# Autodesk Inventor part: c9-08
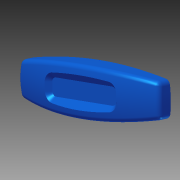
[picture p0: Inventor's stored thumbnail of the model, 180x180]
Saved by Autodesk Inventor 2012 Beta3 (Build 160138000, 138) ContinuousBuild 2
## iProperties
Created: 2010-12
Part Number: c9-08
Material: Default
Document SubType Name: Modeling
Designer: Beta-8540w
Density: 1 g/cm^3
Author: Beta-8540w
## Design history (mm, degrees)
sketch "Sketch1"
  geometry: L1 (-60, -12)-(60, -12); L2 (60, -12)-(60, 12); L3 (60, 12)-(-60, 12); L4 (-60, 12)-(-60, -12); A1 r 350 centre (0, -332.819) between (60, 12) and (-60, 12); A2 r 350 centre (0, 332.819) between (-60, -12) and (60, -12); 3 further points
  constraints: 8 end point, 4 point on circle, 2 centre point, 2 midpoint, 2 parallel, 1 equal radius, 1 horizontal, 1 horizontal alignment, 1 perpendicular, 1 vertical alignment
  dimensions: "d0" = 120 distance of L3.end L2.end; "d1" = 24 distance of L2.end L1.end; "d2" = 350 radius of A1
workplane "Work Plane4"
sketch "Sketch5"
  geometry: L1 (-60, 12)-(-60, -12) reference; L2 (60, -12)-(60, 12) reference; L3 (-58, 10.314)-(-58, -10.314); L4 (58, -10.314)-(58, 10.314); A1 r 350 centre (0, 332.819) between (-60, -12) and (60, -12) reference; A2 r 350 centre (0, -332.819) between (60, 12) and (-60, 12) reference; A3 r 348 centre (0, 332.819) between (-58, -10.314) and (58, -10.314); A4 r 348 centre (0, -332.819) between (58, 10.314) and (-58, 10.314); 1 further point
  constraints: 4 end point, 4 point on circle, 2 centre point, 3 other
  dimensions: "d37" = 2 distance between parallel lines of L2 L4
sketch "Sketch6"
  geometry: L1 (-60, 0)-(60, 0); L2 (60, 0)-(58.843, 22.085); L3 (-60, 0)-(-58.779, 23.307); A1 r 691.758 centre (630.81, -36.204) between (-60, 0) and (-58, -100); A2 r 691.758 centre (-630.81, -36.204) between (58, -100) and (60, 0); 1 further point
  constraints: 6 end point, 4 point on circle, 2 centre point, 2 tangent, 1 horizontal
  dimensions: "d53" = 87 deg angle of L1 L3; "d54" = 87 deg angle of L1 L2 (= d53)
sketch "Sketch7"
  geometry: L1 (17.181, 0)-(12, 0) reference; L2 (15.181, -100)-(10.314, -100) reference; L3 (17.181, 0)-(16.768, 11.838); A1 r 911.322 centre (-893.585, -31.805) between (15.181, -100) and (17.181, 0); 1 further point
  constraints: 2 end point, 2 point on circle, 1 centre point, 1 tangent
  dimensions: "d56" = 88 deg angle of L1 L3
feature "LoftSrf2" sketch "Sketch5", "Sketch6", "Sketch7" dims "d57" = 0, "d58" = 90 deg, "d59" = 0, "d60" = 90 deg, "d61" = 0, "d62" = 90 deg, "d63" = 0, "d64" = 90 deg, "d65" = 0, "d66" = 90 deg
sketch "Sketch2"
  geometry: L1 (-75, -16)-(75, -16); L2 (-75, -60)-(75, -60); A1 r 183.781 centre (0, -183.781) between (75, -16) and (-75, -16); 2 further points
  constraints: 4 end point, 3 point on circle, 1 centre point, 1 coincident, 1 horizontal, 1 parallel
  dimensions: "d5" = 16 distance from line of point (0, 0) L1; "d7" = 60 distance from line of point (0, 0) L2; "d55" = 150 distance of L1.start L1.end
feature "RevolutionSrf1" sketch "Sketch2" dims angle "d8" = 40 deg
patch "Boundary Patch1" dims "d13" = 0, "d67" = 0, "d68" = 0, "d69" = 0, "d70" = 0
workplane "Work Plane1"
sketch "Sketch3"
  geometry: L1 (52, -85)-(52, -73); L2 (38, -73)-(38, -85); A1 r 7 centre (45, -73) between (52, -73) and (38, -73); A2 r 7 centre (45, -85) between (38, -85) and (52, -85); 1 further point
  constraints: 4 end point, 4 point on circle, 4 tangent, 2 centre point, 1 parallel, 1 vertical
  dimensions: "d15" = 12 distance of L1.start L1.end; "d16" = 7 radius of A1; "d50" = 45 horizontal distance of A1.centre point (0, 0); "d51" = 85 vertical distance of point (0, 0) A2.centre
extrude_surface "ExtrusionSrf2" sketch "Sketch3" dims "d19" = 14, "d20" = 5 deg
pattern_linear "Rectangular Pattern1" dims "d23" = 90
workplane "Work Plane2"
feature "Sculpt1"
sketch "Sketch4"
  geometry: L1 (-24.5, 6)-(24.5, 6); L2 (27.5, 3)-(27.5, -3); L3 (24.5, -6)-(-24.5, -6); L4 (-27.5, -3)-(-27.5, 3); A1 r 3 centre (-24.5, 3) between (-24.5, 6) and (-27.5, 3); A2 r 3 centre (24.5, 3) between (27.5, 3) and (24.5, 6); A3 r 3 centre (24.5, -3) between (24.5, -6) and (27.5, -3); A4 r 3 centre (-24.5, -3) between (-27.5, -3) and (-24.5, -6); 6 further points
  constraints: 8 end point, 8 point on circle, 8 tangent, 6 point on line, 4 centre point, 3 equal radius, 2 midpoint, 2 parallel, 1 horizontal, 1 horizontal alignment, 1 perpendicular, 1 vertical alignment
  dimensions: "d28" = 55 distance of point (27.5, -6) point (-27.5, -6); "d29" = 12 distance of point (27.5, 6) point (27.5, -6); "d30" = 3 radius of A1
extrude_surface "ExtrusionSrf6" sketch "Sketch4" dims "d31" = 14, "d32" = 45 deg
patch "Boundary Patch2" dims "d33" = 0, "d34" = 0
fillet "Fillet1" dims "d79" = 4, "d80" = 3, "d81" = 1
feature "Sculpt2"
node "Splitting Plane 1"
shell "Shell1" dims "d83" = 2
split "Split1"
  body "Solid1"
feature "Lip1" dims "d188" = 1, "d189" = 1, "d190" = 0, "d191" = 0, "d192" = 0, "d193" = 0
feature "Lip2" dims "d194" = 1, "d195" = 1, "d196" = 0, "d197" = 0, "d198" = 0, "d199" = 0.5
split "Split3"
  node "Back"
sketch "Sketch9"
  geometry: L1 (50.167, -73)-(50.167, -85) reference; L2 (39.833, -85)-(39.833, -73) reference; L3 (45, -73)-(45, -85); L4 (45, -85)-(39.833, -85); A1 r 5.167 centre (45, -73) between (50.167, -73) and (39.833, -73) reference; A2 r 5.167 centre (45, -85) between (39.833, -85) and (50.167, -85) reference; 5 further points
  constraints: 4 end point, 1 horizontal, 1 midpoint, 1 parallel, 1 perpendicular, 1 vertical, 3 other
  dimensions: "d86" = 90 distance of point (45, -79) point (-45, -79); "d89" = 40 distance of point (45, -79) point (45, -39)
  node "Projected Loop1"
feature "Boss1" dims "d92" = 0, "d93" = 0, "d94" = 7, "d95" = 2, "d96" = 0.5, "d97" = 6, "d98" = 1.25, "d99" = 3.5, "d100" = 2.5 deg, "d101" = 2.5 deg, "d102" = 2.5 deg, "d103" = 2.5 deg, "d104" = 90 deg, "d107" = 2, "d108" = 2, "d109" = 10, "d110" = 0, "d111" = 10 deg, "d112" = 2.5 deg, "d113" = 0, "d114" = 0, "d115" = 0, "d116" = 360 deg
feature "Boss2" dims "d117" = 3, "d118" = 0, "d119" = 6, "d120" = 3, "d121" = 9.5, "d122" = 2 deg, "d123" = 1 deg, "d126" = 2, "d127" = 2, "d128" = 10, "d129" = 0, "d130" = 10 deg, "d131" = 2.5 deg, "d132" = 0, "d133" = 0, "d134" = 0, "d135" = 360 deg
workplane "Work Plane6"
sketch "Sketch10"
  geometry: L1 (24, -85)-(-24, -85); L2 (-30, -79)-(-30, -51); L3 (-24, -45)-(24, -45); L4 (30, -51)-(30, -79); L5 (54.344, -100)-(-54.344, -100) reference; A1 r 6 centre (-24, -51) between (-24, -45) and (-30, -51); A2 r 6 centre (24, -51) between (30, -51) and (24, -45); A3 r 6 centre (24, -79) between (24, -85) and (30, -79); A4 r 6 centre (-24, -79) between (-30, -79) and (-24, -85); 5 further points
  constraints: 8 end point, 8 point on circle, 8 tangent, 6 point on line, 4 centre point, 3 equal radius, 2 parallel, 1 horizontal, 1 midpoint, 1 perpendicular, 1 vertical alignment
  dimensions: "d137" = 60 distance of point (-30, -45) point (30, -45); "d138" = 40 distance of point (-30, -85) point (-30, -45); "d139" = 15 distance between parallel lines of L5 L1; "d141" = 6 radius of A2
feature "Rest1" sketch "Sketch10" dims "d142" = 5, "d143" = 0, "d144" = 0, "d145" = 0, "d146" = 2 deg, "d147" = 2 deg, "d148" = 2
feature "Rule Fillet1" dims "d149" = 2, "d150" = 1
workplane "Work Plane7"
sketch "Sketch11" dims "d154" = 16, "d155" = 8, "d161" = 10, "d168" = 10
  geometry: L1 (-13, -39.858)-(-13, -90.142); L2 (-25.187, -85)-(29.449, -85); L3 (0, -39.858)-(0, -90.142); L4 (13, -39.858)-(13, -90.142); L5 (-25.187, -77)-(29.449, -77); L6 (-25.187, -69)-(29.449, -69); L7 (-25.187, -61)-(29.449, -61); L8 (-25.187, -53)-(29.449, -53); L9 (-25.187, -45)-(29.449, -45); C1 r 22.5 at (0, -65); 3 further points; 1 other entity
  constraints: 18 end point, 2 coincident, 2 vertical, 1 centre point, 1 horizontal, 1 midpoint, 1 perpendicular, 1 vertical alignment, 23 other
  dimensions: "d152" = 45 diameter of C1; "d153" = 65 distance of point (0, 0) C1.centre; "d158" = 13 distance of L1.start L3.start; "d165" = 8 distance of L2.start L5.start; "d170" = 4 distance from line of L7 point (0, -65)
feature "Grill1" sketch "Sketch11" dims "d173" = 2, "d174" = 0, "d175" = 1, "d176" = 2, "d177" = 0, "d178" = 1, "d179" = 0.5, "d180" = 0, "d181" = 2, "d182" = 1, "d183" = 2 deg, "d184" = 0, "d185" = 88.84492
sketch "Sketch12"
  geometry: L1 (-12.481, -61.203)-(12.401, -61.203); L2 (12.401, -61.203)-(12.401, -68.714); L3 (12.401, -68.714)-(-12.481, -68.714); L4 (-12.481, -68.714)-(-12.481, -61.203); 1 further point
  constraints: 2 other
emboss "Emboss1" sketch "Sketch12" dims "d0" = 120, "d1" = 24, "d2" = 350, "d186" = 0.5, "d187" = 0
sketch "Sketch13"
  geometry: L1 (0, 15.66)-(0, -14.781); 6 further points
  constraints: 2 end point, 1 coincident, 1 point on line, 1 vertical, 4 other
body "Srf2"
body "Srf3"
body "Srf4"
body "Srf5"
body "Srf6"
body "Srf7"
body "Srf8"
body "Srf9"
body "Srf11"
feature "Stitch Surface1"
body "Srf12"
extrude_surface "ExtrusionSrf3"
extrude_surface "ExtrusionSrf4"
extrude_surface "ExtrusionSrf5"
node "Front"
node "Back - Top"
node "Back - Bottom"
other parameters: "d14" = -24, "d52" = -6, "d171" = 1, "d172" = 2
